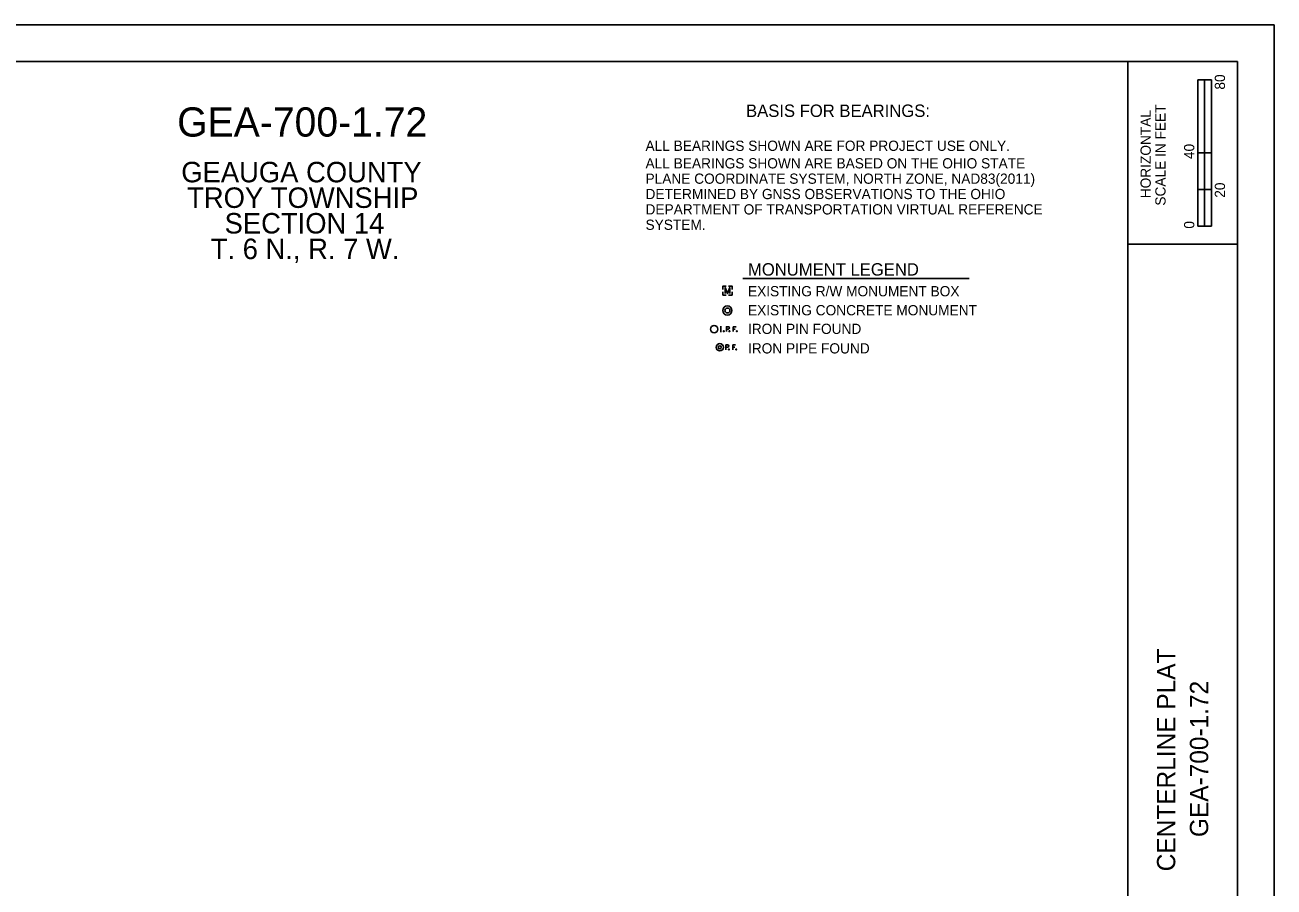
# Model space of a CAD drawing. Extents: x -4.9 to 34, y -1.2 to 22.
# Drawn here: x 16.92 to 34, y 10.21 to 22 of the extents above; entities that cross this region are included whole.
import ezdxf

# ---------------------------------------------------------------- set-up
doc = ezdxf.new("R2010")
doc.units = 0
for name, color, linetype in [('SH_Border', 7, 'Continuous'), ('SH_Cut_Line', 7, 'Continuous'), ('SH_Data', 7, 'Continuous'), ('SH_Text', 7, 'Continuous')]:
    doc.layers.add(name, color=color, linetype=linetype)

msp = doc.modelspace()

# ---------------------------------------------------------------- linework, layer by layer
at = {"layer": 'SH_Border'}
for p, q in [((32, 0.5), (32, 21.5)), ((32, 19), (33.5, 19))]:
    msp.add_line(p, q, dxfattribs=at)
msp.add_lwpolyline([(1.5, 21.5), (33.5, 21.5), (33.5, 0.5), (1.5, 0.5)], close=True, dxfattribs=at)
at = {"layer": 'SH_Cut_Line'}
msp.add_lwpolyline([(0, 0), (34, 0), (34, 22), (0, 22)], close=True, dxfattribs=at)
at = {"layer": 'SH_Data'}
for p, q in [((32.957, 19.25), (32.957, 21.25)), ((33.144, 21.25), (32.957, 21.25)), ((32.957, 20.25), (32.957, 21.25)), ((32.957, 21.25), (33.05, 21.25)), ((33.05, 21.25), (33.051, 21.25)), ((33.051, 21.25), (33.051, 20.25)), ((33.144, 21.25), (33.144, 19.25)), ((33.051, 20.25), (32.957, 20.25)), ((33.143, 20.25), (33.05, 20.25)), ((33.05, 20.25), (33.05, 19.75)), ((33.143, 19.75), (33.143, 20.25)), ((33.05, 19.75), (32.957, 19.75)), ((32.957, 19.75), (32.957, 19.25)), ((33.05, 19.25), (33.05, 19.75)), ((33.05, 19.75), (33.143, 19.75)), ((33.144, 19.25), (32.957, 19.25)), ((32.957, 19.25), (33.05, 19.25))]:
    msp.add_line(p, q, dxfattribs=at)
at = {"layer": 'SH_Text'}
for p, q in [((26.739, 18.534), (29.832, 18.534)), ((26.527, 18.368), (26.527, 18.368)), ((26.429, 17.873), (26.445, 17.873)), ((26.429, 17.873), (26.445, 17.873)), ((26.429, 17.806), (26.445, 17.806)), ((26.437, 17.806), (26.437, 17.873)), ((26.514, 17.841), (26.54, 17.841)), ((26.607, 17.806), (26.607, 17.873)), ((26.607, 17.873), (26.646, 17.873)), ((26.607, 17.841), (26.635, 17.841)), ((26.506, 17.593), (26.533, 17.593)), ((26.6, 17.559), (26.6, 17.625)), ((26.6, 17.625), (26.638, 17.625)), ((26.6, 17.593), (26.627, 17.593))]:
    msp.add_line(p, q, dxfattribs=at)
for points in [[(26.465, 18.383), (26.465, 18.43), (26.512, 18.43)], [(26.512, 18.305), (26.465, 18.305), (26.465, 18.352)], [(26.496, 18.326), (26.496, 18.409), (26.527, 18.326), (26.558, 18.409), (26.558, 18.326)], [(26.542, 18.43), (26.59, 18.43), (26.59, 18.383)], [(26.59, 18.352), (26.59, 18.305), (26.542, 18.305)], [(26.54, 17.873), (26.514, 17.873), (26.514, 17.806)], [(26.533, 17.625), (26.506, 17.625), (26.506, 17.559)]]:
    msp.add_lwpolyline(points, dxfattribs=at)
for centre, radius in [((26.527, 18.095), 0.0625), ((26.527, 18.095), 0.0333), ((26.345, 17.84), 0.05), ((26.477, 17.811), 0.00583), ((26.554, 17.811), 0.00583), ((26.656, 17.811), 0.00583), ((26.423, 17.592), 0.05), ((26.423, 17.592), 0.0206), ((26.547, 17.563), 0.00583), ((26.648, 17.563), 0.00583)]:
    msp.add_circle(centre, radius, dxfattribs=at)
for centre in [(26.538, 17.857), (26.531, 17.609)]:
    msp.add_arc(centre, 0.0162, 278.8803, 81.1197, dxfattribs=at)

# ---------------------------------------------------------------- texts
at = {"layer": 'SH_Data'}
for s, height, p in [('80', 0.14, (33.33, 21.116)), ('SCALE IN FEET', 0.14, (32.517, 19.529)), ('HORIZONTAL', 0.14, (32.315, 19.63)), ('40', 0.14, (32.91, 20.166)), ('20', 0.14, (33.33, 19.637)), ('0', 0.14, (32.91, 19.214)), ('CENTERLINE PLAT', 0.25, (32.65, 10.425)), ('GEA-700-1.72', 0.25, (33.1, 10.893))]:
    msp.add_text(s, height=height, rotation=90, dxfattribs=at).set_placement(p)
at = {"layer": 'SH_Text'}
for s, height, p in [('GEA-700-1.72', 0.4, (19.004, 20.473)), ('BASIS FOR BEARINGS:', 0.17, (26.782, 20.742)), ('ALL BEARINGS SHOWN ARE FOR PROJECT USE ONLY.', 0.14, (25.407, 20.278)), ('ALL BEARINGS SHOWN ARE BASED ON THE OHIO STATE', 0.14, (25.407, 20.038)), ('GEAUGA COUNTY', 0.28, (19.06, 19.848)), ('PLANE COORDINATE SYSTEM, NORTH ZONE, NAD83(2011)', 0.14, (25.407, 19.828)), ('TROY TOWNSHIP', 0.28, (19.14, 19.498)), ('DETERMINED BY GNSS OBSERVATIONS TO THE OHIO', 0.14, (25.407, 19.618)), ('DEPARTMENT OF TRANSPORTATION VIRTUAL REFERENCE', 0.14, (25.407, 19.408)), ('SECTION 14', 0.28, (19.652, 19.148)), ('SYSTEM.', 0.14, (25.407, 19.198)), ('T. 6 N., R. 7 W.', 0.28, (19.463, 18.798)), ('MONUMENT LEGEND', 0.17, (26.808, 18.572)), ('EXISTING R/W MONUMENT BOX', 0.14, (26.808, 18.289)), ('EXISTING CONCRETE MONUMENT', 0.14, (26.808, 18.029)), ('IRON PIN FOUND', 0.14, (26.808, 17.774)), ('IRON PIPE FOUND', 0.14, (26.808, 17.507))]:
    msp.add_text(s, height=height, dxfattribs=at).set_placement(p)

doc.saveas('drawing.dxf')
